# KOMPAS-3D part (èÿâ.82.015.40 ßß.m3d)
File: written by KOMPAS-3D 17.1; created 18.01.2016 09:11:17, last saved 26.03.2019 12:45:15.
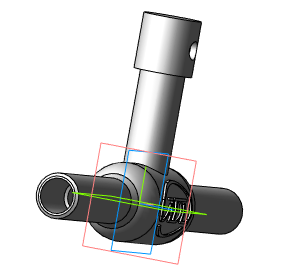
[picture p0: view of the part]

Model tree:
1. Операция без истории:5  (labels: Сталь 20  ГОСТ 1050-88)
